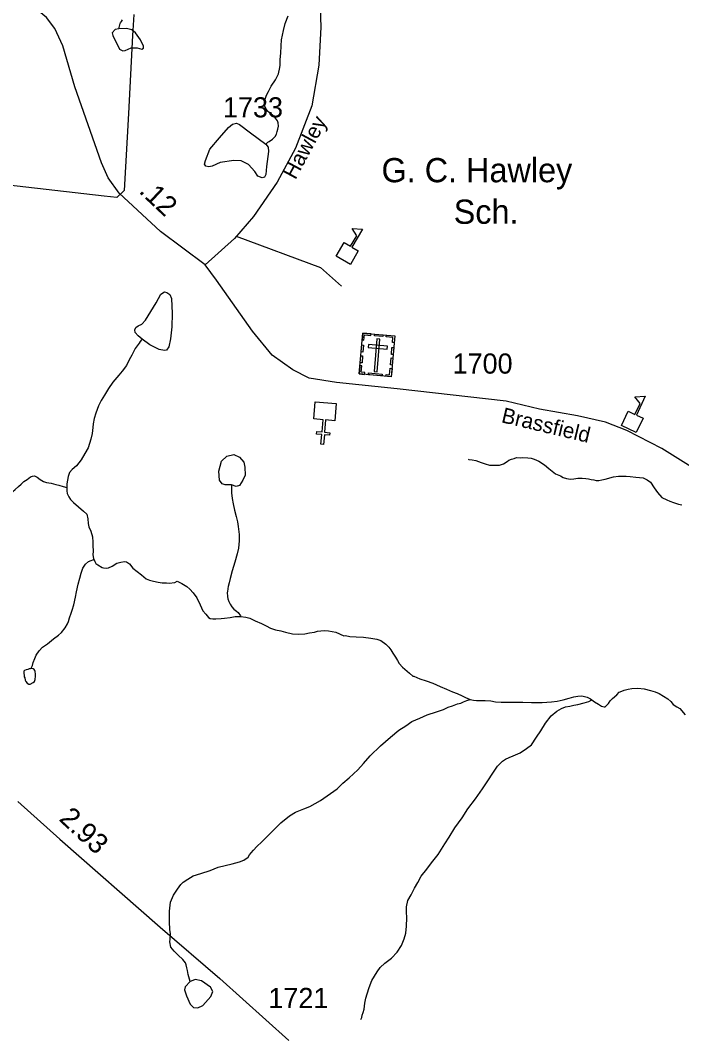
# Model space of a CAD drawing. Extents: x 2056842 to 2160602, y 826753 to 1016856.
# Drawn here: x 2095148 to 2099244, y 853660 to 859964 of the extents above; entities that cross this region are included whole.
import ezdxf

# ---------------------------------------------------------------- set-up
doc = ezdxf.new("R2010")
doc.units = 0
for name, color, linetype in [('Exist Boundary Political City Limit New', 7, 'Continuous'), ('Exist Cultural Cemetery CELL', 7, 'Continuous'), ('Exist Cultural Church CELL', 7, 'Continuous'), ('Exist Cultural Educational Facility High CELL', 7, 'Continuous'), ('Exist Cultural Educational Facility High Label', 7, 'Continuous'), ('Exist Hydrographic Creek Single Shore', 7, 'Continuous'), ('Exist Hydrographic Misc Water Feature', 7, 'Continuous'), ('Exist Road Non-System Type 51', 7, 'Continuous'), ('Exist Road Secondary Mileage Hundredths English Label', 7, 'Continuous'), ('Exist Road Secondary Type 51 Attributed', 7, 'Continuous'), ('Exist Road Secondary Type 51 Label', 7, 'Continuous'), ('Exist Road Secondary Type 51 Number Label', 7, 'Continuous'), ('Map Preparation Boundary City Limit Buffer Line', 7, 'Continuous')]:
    doc.layers.add(name, color=color, linetype=linetype)

msp = doc.modelspace()

# ---------------------------------------------------------------- linework, layer by layer
at = {"layer": 'Exist Boundary Political City Limit New'}
msp.add_lwpolyline([(2095849.9, 860000), (2095844.8, 859902.2), (2095843.1, 859871.1), (2095838.9, 859789.4), (2095817.8, 859386.1), (2095791.2, 858909.4), (2095744.6, 858866.4), (2095668, 858875.1), (2095000, 858950.6)], dxfattribs=at)
at = {"layer": 'Exist Cultural Cemetery CELL'}
for points in [[(2097268.9, 858026.4), (2097467.3, 858009.4), (2097445.6, 857755.7), (2097247.2, 857772.7)], [(2097265.2, 857983.3), (2097276.5, 857982.3), (2097279.3, 858014.4), (2097319.7, 858010.9), (2097320.6, 858022), (2097268.9, 858026.4)], [(2097375.1, 857987.9), (2097356.4, 857989.5), (2097339.2, 857787.5), (2097357.8, 857785.9)], [(2097342.7, 858020.1), (2097394.4, 858015.7), (2097393.4, 858004.3), (2097341.8, 858008.7)], [(2097463.7, 857966.2), (2097452.4, 857967.2), (2097455.1, 857999.3), (2097414.7, 858002.7), (2097415.6, 858013.8), (2097467.3, 858009.4)], [(2097258.9, 857909.4), (2097262.6, 857952.5), (2097273.9, 857951.6), (2097270.2, 857908.4)], [(2097303.8, 857955.1), (2097302.2, 857936.5), (2097419.5, 857926.5), (2097421.1, 857945.1)], [(2097446.1, 857894.4), (2097449.8, 857937.6), (2097461.1, 857936.6), (2097457.4, 857893.4)], [(2097253.1, 857842.4), (2097256.8, 857885.6), (2097268.2, 857884.6), (2097264.5, 857841.4)], [(2097440.4, 857828.7), (2097444.1, 857871.9), (2097455.5, 857870.9), (2097451.8, 857827.7)], [(2097280.2, 857769.9), (2097281.2, 857781.4), (2097259.2, 857783.3), (2097262.7, 857823.5), (2097251.6, 857824.5), (2097247.2, 857772.8)], [(2097412.6, 857758.6), (2097413.6, 857770), (2097435.5, 857768.1), (2097438.9, 857808.4), (2097450, 857807.5), (2097445.6, 857755.7)], [(2097305.4, 857779.3), (2097390, 857772), (2097389, 857760.7), (2097304.5, 857767.9)]]:
    msp.add_lwpolyline(points, close=True, dxfattribs=at)
at = {"layer": 'Exist Cultural Church CELL'}
msp.add_lwpolyline([(2097095.7, 857482.9), (2097039, 857487.6), (2097032.4, 857411.8), (2097064.3, 857409), (2097063, 857393.1), (2097031.1, 857395.9), (2097025.9, 857336), (2097010, 857337.3), (2097015.1, 857397.2), (2096983.2, 857400), (2096984.6, 857415.9), (2097016.5, 857413.2), (2097023, 857489), (2096965.6, 857494.1), (2096974.7, 857600.1), (2097104.8, 857588.9)], close=True, dxfattribs=at)
at = {"layer": 'Exist Cultural Educational Facility High CELL'}
for points in [[(2097104.3, 858502.5), (2097153.6, 858587.1), (2097193.4, 858563.9), (2097231.2, 858628.8), (2097202.8, 858673.4), (2097266.4, 858670.1), (2097201.7, 858559.1), (2097241.4, 858535.9), (2097192.1, 858451.3)], [(2098871.4, 857453.2), (2098913.2, 857541.8), (2098954.8, 857522.2), (2098986.8, 857590.1), (2098954.6, 857632.1), (2099018.2, 857634.3), (2098963.5, 857518.1), (2099005.1, 857498.5), (2098963.4, 857409.9)]]:
    msp.add_lwpolyline(points, close=True, dxfattribs=at)
at = {"layer": 'Exist Hydrographic Creek Single Shore'}
for points in [[(2095034.8, 857051.2), (2095048.9, 857047), (2095068.6, 857043.2), (2095084.8, 857043.2), (2095100.8, 857045.2), (2095116.8, 857057.4), (2095136.9, 857075.4), (2095152.9, 857089.6), (2095168.7, 857105.5), (2095190.6, 857119.6), (2095210.7, 857135.7), (2095222.8, 857139.5), (2095234.7, 857141.8), (2095252.3, 857133.8), (2095270.4, 857119.7), (2095290.3, 857106.1), (2095310.6, 857099.8), (2095338.2, 857096), (2095366.7, 857088.1), (2095386.4, 857084.2), (2095412.9, 857076.2), (2095436.5, 857070.2)], [(2095436.5, 857070.2), (2095436.7, 857048.2), (2095438.7, 857032.5), (2095449, 857012.3), (2095458.6, 856994.6), (2095476.9, 856976.4), (2095507.2, 856948.7), (2095539, 856922.8), (2095558.9, 856904.8), (2095565.4, 856874.6), (2095567.1, 856846.7), (2095571.6, 856824.9), (2095585.5, 856798.9), (2095595.6, 856762.9), (2095597.4, 856730.9), (2095596, 856708.8), (2095598, 856674.8), (2095597.8, 856651), (2095601.7, 856628.8), (2095604, 856624.8)], [(2095604, 856624.8), (2095609.7, 856611), (2095615.9, 856599.1), (2095628.2, 856589.1), (2095654, 856573), (2095663.9, 856571.1), (2095680.3, 856569.1), (2095694.2, 856571), (2095716.2, 856581.4), (2095746.1, 856599.3), (2095769.9, 856607.4), (2095793.9, 856611.5), (2095806, 856607.6), (2095824, 856595.5), (2095843.9, 856569.8), (2095872.2, 856547.7), (2095898.2, 856527.9), (2095926.5, 856504.1), (2095948.5, 856495.9), (2095972.7, 856488.2), (2096002.2, 856482.1), (2096026.4, 856478.5), (2096052.6, 856478.2), (2096070.5, 856476.3), (2096104.3, 856480.5), (2096118.5, 856488.5), (2096148.4, 856474.6), (2096178.1, 856456.7), (2096198.6, 856439), (2096218.3, 856416.9), (2096240.7, 856385.1), (2096261, 856341.1), (2096278.8, 856305.1), (2096296.9, 856283.3), (2096313.1, 856263.4), (2096323.1, 856257.4), (2096339.3, 856255.4), (2096358.8, 856255.2), (2096391.2, 856257.6), (2096413.1, 856259.6), (2096447, 856263.8), (2096479, 856269.9), (2096513, 856269.6)], [(2096513, 856269.6), (2096545, 856266), (2096569.2, 856259.9), (2096603.2, 856242.1), (2096640.9, 856226.3), (2096671.3, 856212.4), (2096696.9, 856198.3), (2096728.9, 856186.6), (2096761.1, 856180.5), (2096790.8, 856172.7), (2096833.3, 856162.6), (2096873.5, 856161), (2096909.6, 856162.8), (2096939.1, 856169.3), (2096969.4, 856173.2), (2096989.1, 856179.2), (2097009, 856181.4), (2097033.2, 856183.5), (2097057, 856181.5), (2097101.3, 856173.5), (2097151.3, 856149.8), (2097161.4, 856151.9), (2097189.3, 856146), (2097227.2, 856143.9), (2097273.1, 856142.2), (2097319.1, 856136.5), (2097355.1, 856128.6), (2097381.4, 856120.5), (2097411.3, 856098.6), (2097431.2, 856080.6), (2097443.1, 856062.9), (2097455.4, 856042.8), (2097471.6, 856016.8), (2097483.5, 855996.7), (2097493.8, 855979), (2097515.7, 855955), (2097544, 855931.2), (2097557.7, 855919.3), (2097579.9, 855901), (2097584.2, 855899.1), (2097621.9, 855883.2), (2097661.9, 855871.5), (2097702.3, 855855.7), (2097748.2, 855835.7), (2097788, 855819.9), (2097824.1, 855803.9), (2097854.4, 855792), (2097884, 855778.2), (2097906.1, 855768.4), (2097934.4, 855756.4)], [(2098688, 855752.5), (2098704.2, 855740.7), (2098728.4, 855726.9), (2098748.5, 855715), (2098764.5, 855708.9), (2098770.2, 855710.8), (2098790.1, 855731), (2098802.2, 855747), (2098815.9, 855761.1), (2098842.2, 855785.2), (2098858, 855801), (2098873.8, 855807.2), (2098887.9, 855813.1), (2098911.9, 855819.2), (2098936.1, 855823.3), (2098972.2, 855825.5), (2099011.8, 855821.6), (2099051.7, 855811.8), (2099079.8, 855803.9), (2099105.9, 855791.9), (2099132.1, 855776.1), (2099158.4, 855760), (2099176.2, 855742.3), (2099192.4, 855724.4), (2099214.1, 855710.1), (2099232.6, 855700.4), (2099266.2, 855660.5)], [(2097934.4, 855756.4), (2097954.1, 855750.5), (2097972.6, 855748.6), (2097994.3, 855748.5), (2098026.5, 855748.5), (2098062.4, 855746.7), (2098090.7, 855740.8), (2098126.5, 855739), (2098164.3, 855739), (2098214.5, 855739.1), (2098260.4, 855739.5), (2098314.4, 855737.3), (2098380.4, 855735.9), (2098438.6, 855740), (2098473.9, 855746), (2098510.2, 855753.9), (2098547.9, 855764.4), (2098576, 855772.4), (2098600.2, 855776.4), (2098626.1, 855778.6), (2098650, 855772.5), (2098658.2, 855770.5), (2098680, 855758.6), (2098688, 855752.5)]]:
    msp.add_lwpolyline(points, dxfattribs=at)
at = {"layer": 'Exist Hydrographic Misc Water Feature'}
for points in [[(2095757.7, 859911.4), (2095765.6, 859945), (2095768, 859949.1), (2095773.6, 859957.2), (2095781.6, 859966.9)], [(2096668, 859196), (2096674, 859204), (2096681.7, 859210.1), (2096688.1, 859214), (2096709.8, 859228.2), (2096718, 859235.8), (2096725.6, 859244), (2096733.6, 859258.2), (2096739.6, 859276), (2096743.7, 859290), (2096747.4, 859308.1), (2096745.7, 859328.2), (2096741.6, 859341.9), (2096735.3, 859350.1), (2096721.3, 859366), (2096709.4, 859375.9), (2096679.3, 859402), (2096664.9, 859425.7), (2096661.2, 859438), (2096659.4, 859447.6), (2096664.9, 859476), (2096672.7, 859500), (2096684.8, 859523.7), (2096702.5, 859555.9), (2096728.7, 859596.2), (2096746.5, 859632), (2096756.2, 859671.9), (2096756.4, 859686.1), (2096758.2, 859722), (2096762.3, 859761.9), (2096764.2, 859806.2), (2096765.8, 859844.2), (2096777.5, 859902), (2096787.6, 859944.4), (2096807.4, 859992)], [(2095757.7, 859911.4), (2095735, 859907.6), (2095717.2, 859887.3), (2095721, 859870.8), (2095762.8, 859784.7), (2095781.8, 859774.6), (2095797, 859777.1), (2095835, 859794.8), (2095871.7, 859793.6), (2095900.8, 859784.7), (2095909.7, 859792.3), (2095911, 859803.7), (2095892, 859843), (2095861.6, 859886), (2095837.5, 859905), (2095804.6, 859913.9), (2095757.7, 859911.4)], [(2096668, 859196), (2096682, 859177.8), (2096684.6, 859151.2), (2096671.9, 859058.7), (2096669.4, 859008.1), (2096660.5, 858992.9), (2096646.6, 858989.1), (2096618.7, 858997.9), (2096601, 859027.1), (2096560.5, 859071.4), (2096516.2, 859094.2), (2096470.6, 859096.7), (2096385.8, 859084.1), (2096335.1, 859061.3), (2096316.1, 859056.2), (2096297.1, 859061.3), (2096289.5, 859072.7), (2096294.6, 859096.7), (2096322.5, 859165.2), (2096380.7, 859236.1), (2096436.4, 859299.5), (2096463, 859321), (2096487.1, 859326.1), (2096506, 859318.5), (2096574.4, 859266.5), (2096668, 859196)], [(2095901.6, 857989.1), (2095878.1, 858009.7), (2095859.1, 858030), (2095856.5, 858046.5), (2095862.9, 858060.4), (2095876.8, 858070.6), (2095899.6, 858082), (2095922.4, 858106), (2095989.5, 858213.7), (2096018.6, 858266.9), (2096041.4, 858280.9), (2096055.3, 858278.3), (2096074.3, 858265.7), (2096083.2, 858240.3), (2096088.2, 858147.8), (2096085.7, 858064.2), (2096078.1, 857990.7), (2096068, 857940.1), (2096054.1, 857921.1), (2096040.1, 857917.3), (2096008.5, 857923.6), (2095950.2, 857954), (2095901.6, 857989.1)], [(2095901.6, 857989.1), (2095898, 857983.8), (2095889.8, 857973.6), (2095883.5, 857963.7), (2095872, 857947.6), (2095859.9, 857931.6), (2095838, 857889.4), (2095822, 857859.4), (2095804.5, 857825.5), (2095778.5, 857789.3), (2095758.2, 857765.2), (2095720.9, 857721.3), (2095694.8, 857683.1), (2095669.2, 857641.1), (2095648.9, 857608.9), (2095631.1, 857575.1), (2095615.1, 857530.8), (2095605.2, 857497), (2095599.5, 857464.7), (2095597.6, 857440.6), (2095593.7, 857404.6), (2095583.5, 857368.8), (2095568.1, 857314.8), (2095548, 857280.5), (2095524.4, 857240.7), (2095496.1, 857204.4), (2095468.5, 857180.6), (2095452.7, 857162.3), (2095444.5, 857138.4), (2095440.4, 857114.2), (2095436.3, 857092.5), (2095436.5, 857070.2)], [(2096455, 857084.9), (2096416.2, 857085.2), (2096398.4, 857091.5), (2096382, 857115.6), (2096378.2, 857171.3), (2096394.6, 857233.4), (2096427.6, 857263.8), (2096469.4, 857273.9), (2096504.8, 857256.2), (2096532.7, 857225.8), (2096537.7, 857195.4), (2096540.3, 857144.7), (2096525.1, 857114.3), (2096506.1, 857082.6), (2096484.5, 857076.3), (2096455, 857084.9)], [(2097921.7, 857244.2), (2097925.6, 857242), (2097945.7, 857240.1), (2097969.5, 857236.1), (2098002.1, 857224.3), (2098027.9, 857216.3), (2098053.8, 857208.3), (2098084.1, 857206.6), (2098115.9, 857208.6), (2098139.7, 857216.8), (2098163.9, 857231.1), (2098173.5, 857238.9), (2098189.9, 857244.9), (2098205.9, 857249), (2098221.7, 857255.1), (2098245.7, 857253.1), (2098259.6, 857255), (2098291.6, 857253), (2098311.7, 857251.2), (2098329.8, 857245.3), (2098359.7, 857233.4), (2098395.6, 857209.7), (2098421.6, 857187.5), (2098462, 857153.8), (2098494, 857141.6), (2098509.8, 857132), (2098531.7, 857124.1), (2098555.7, 857120.1), (2098575.6, 857122), (2098601.9, 857126.1), (2098627.7, 857126.2), (2098650, 857124.5), (2098667.9, 857122.6), (2098683.9, 857118.5), (2098699.7, 857116.5), (2098713.8, 857112.4), (2098731.7, 857112.5), (2098749.9, 857116.6), (2098769.6, 857120.9), (2098821.7, 857135), (2098853.9, 857139), (2098899.8, 857139), (2098925.8, 857137.1), (2098959.9, 857133.1), (2099005.6, 857129.4), (2099029.6, 857117.7), (2099051.9, 857101.7), (2099073.9, 857067.5), (2099094, 857037.7), (2099122.3, 857007.9), (2099152.4, 856992), (2099170.5, 856983.9), (2099194.3, 856976.3), (2099224.4, 856966), (2099244.3, 856962.2)], [(2096455, 857084.9), (2096456.8, 857067.7), (2096456.6, 857051.5), (2096456.6, 857035.7), (2096460.5, 857001.4), (2096466.9, 856967.6), (2096474.9, 856929.4), (2096484.9, 856889.8), (2096493.3, 856855.7), (2096497, 856827.5), (2096503.1, 856777.9), (2096503.8, 856739.6), (2096499.9, 856693.6), (2096491.7, 856657.5), (2096475.7, 856607.5), (2096459.9, 856553.6), (2096448.2, 856505.4), (2096440.4, 856479.4), (2096434.3, 856455.6), (2096432.2, 856443.7), (2096430.8, 856421.7), (2096428.3, 856417.6), (2096430.8, 856393.7), (2096432.6, 856379.6), (2096438.6, 856363.7), (2096446.6, 856345.8), (2096458.9, 856329.7), (2096471, 856315.7), (2096478.7, 856309.7), (2096486.7, 856303.6), (2096497, 856293.9), (2096511.1, 856273.6), (2096513, 856269.6)], [(2095214.2, 855947.9), (2095216, 855953.7), (2095222.4, 855965.7), (2095227.9, 855983.9), (2095238.2, 856010), (2095245.8, 856029.9), (2095263.8, 856056), (2095285.5, 856079.9), (2095315.7, 856100.1), (2095353.4, 856130.4), (2095383.4, 856154.3), (2095403.5, 856170.4), (2095425, 856200.4), (2095439.3, 856224.6), (2095447.1, 856238.4), (2095452.9, 856260.6), (2095462.9, 856290.8), (2095468.9, 856308.5), (2095478.9, 856342.7), (2095488.8, 856388.7), (2095496.5, 856422.8), (2095506.6, 856470.8), (2095516.4, 856506.7), (2095524.2, 856538.7), (2095533.9, 856568.5), (2095552.3, 856594.9), (2095570, 856610.9), (2095585.7, 856617.1), (2095597.8, 856620.9), (2095604, 856624.8)], [(2095214.2, 855947.9), (2095208.4, 855945.9), (2095202.1, 855945.7), (2095194.1, 855941.6), (2095184.5, 855939.8), (2095174.4, 855935.6), (2095169.9, 855931.8), (2095170.1, 855917.6), (2095172.4, 855903.5), (2095172.4, 855895.8), (2095176.1, 855889.5), (2095178.5, 855875.8), (2095182.4, 855865.9), (2095190.4, 855855.7), (2095200.5, 855849.7), (2095208.4, 855849.7), (2095226.5, 855860), (2095236.1, 855867.9), (2095240.2, 855879.8), (2095242.3, 855899.8), (2095242.3, 855914), (2095240.4, 855926), (2095240, 855931.8), (2095238.2, 855935.7), (2095234.1, 855942), (2095227.9, 855945.8), (2095214.2, 855947.9)], [(2096199.7, 854007.1), (2096188, 854051.1), (2096183.7, 854075.3), (2096179.8, 854092.9), (2096175.5, 854111), (2096169.9, 854123.2), (2096153.7, 854143.1), (2096151.3, 854147.1), (2096127.5, 854169), (2096101.5, 854194.8), (2096079.5, 854220.5), (2096073.4, 854252.7), (2096075, 854270.7), (2096077, 854302.9), (2096074.8, 854330.7), (2096071.1, 854376.8), (2096070.9, 854444.5), (2096078.7, 854498.6), (2096096.1, 854543), (2096120.3, 854580.7), (2096142.1, 854609.1), (2096156.2, 854622.7), (2096185.9, 854640.9), (2096217.7, 854663.3), (2096265.9, 854677.1), (2096323.9, 854695.5), (2096374, 854715.5), (2096415.6, 854725.9), (2096459.7, 854737.8), (2096505.4, 854750), (2096531.9, 854760.2), (2096559.5, 854778.3), (2096567.7, 854792.1), (2096577.4, 854804.4), (2096591.5, 854822.2), (2096613.5, 854844.4), (2096643.2, 854872.3), (2096647.3, 854876.6), (2096693, 854922.4), (2096724.8, 854954.5), (2096761.1, 854990.8), (2096814.6, 855035), (2096852.4, 855056.9), (2096904.6, 855077.4), (2096940.5, 855091.4), (2097006.3, 855129.3), (2097048, 855157.5), (2097110.3, 855202), (2097146, 855235.9), (2097183.9, 855270), (2097237.4, 855320.3), (2097273.5, 855358.3), (2097315.6, 855406.2), (2097379.5, 855468.8), (2097441.1, 855522.8), (2097492.7, 855564.8), (2097534.8, 855592.9), (2097572.7, 855619.2), (2097622.9, 855639.2), (2097668.7, 855659.5), (2097726.5, 855679.5), (2097768.7, 855693.8), (2097798.3, 855708), (2097824.3, 855715.9), (2097856.1, 855728.1), (2097876.4, 855732.3), (2097892.6, 855740), (2097914.1, 855750.1), (2097934.4, 855756.4)], [(2097256.7, 853772.3), (2097262.5, 853784.4), (2097266.1, 853798.4), (2097272.1, 853816.6), (2097278.4, 853836.4), (2097282.1, 853874.3), (2097288.1, 853904.6), (2097296.3, 853930.6), (2097308, 853970.6), (2097326, 854014.6), (2097357.4, 854068.6), (2097377.5, 854094.8), (2097405.4, 854121), (2097447.6, 854153.2), (2097481.2, 854189.1), (2097509.1, 854231.1), (2097525.1, 854271.3), (2097535, 854307.1), (2097540.5, 854351.3), (2097542.6, 854401.3), (2097540.3, 854439.4), (2097540.1, 854471.5), (2097548.1, 854509.2), (2097568.2, 854545.5), (2097589.7, 854585.3), (2097609.8, 854621.6), (2097631.3, 854659.7), (2097665.6, 854703.6), (2097695.1, 854743.8), (2097735.3, 854795.7), (2097776.9, 854860), (2097804.8, 854902), (2097838.7, 854960.2), (2097884.8, 855022.2), (2097920.5, 855078.5), (2097968.2, 855140.6), (2098010.1, 855200.8), (2098043.9, 855250.9), (2098073.6, 855298.7), (2098103.4, 855342.9), (2098135.2, 855372.9), (2098153.4, 855385.2), (2098175.6, 855395.2), (2098201.2, 855407.2), (2098243.4, 855425.1), (2098283.4, 855451.5), (2098313.3, 855475.4), (2098344.9, 855521.7), (2098371, 855561.6), (2098400.9, 855607.8), (2098436.6, 855653.9), (2098470.4, 855684.1), (2098500.4, 855700.2), (2098524.6, 855710), (2098552.4, 855714.2), (2098576.4, 855720.4), (2098600.4, 855724.4), (2098640.4, 855734.6), (2098670.1, 855742.7), (2098688, 855752.5)], [(2096199.7, 854007.1), (2096169.3, 853975.4), (2096164.2, 853955.1), (2096176.9, 853919.6), (2096199.7, 853866.4), (2096221.2, 853846.2), (2096247.8, 853844.9), (2096278.2, 853858.8), (2096328.8, 853914.6), (2096340.2, 853945), (2096326.3, 853972.9), (2096270.6, 854012.1), (2096230, 854019.7), (2096216.1, 854014.7), (2096199.7, 854007.1)]]:
    msp.add_lwpolyline(points, dxfattribs=at)
at = {"layer": 'Exist Road Non-System Type 51'}
msp.add_lwpolyline([(2096485.6, 858626.1), (2097007.6, 858432.9), (2097136.4, 858316.5)], dxfattribs=at)
at = {"layer": 'Exist Road Secondary Type 51 Attributed'}
for points in [[(2096819.9, 863367.2), (2096834.5, 863240.4), (2096830.3, 862999.4), (2096827.2, 862241.8), (2096848, 861855.2), (2096876, 861363.7), (2096962.2, 860541.7), (2097001.6, 860167.6), (2097010, 859922.4), (2096996.5, 859686.5), (2096952.8, 859435), (2096853.1, 859173.1), (2096737.9, 858962.2), (2096592.5, 858748.1), (2096474.1, 858613), (2096292.4, 858449.9)], [(2096292.4, 858449.9), (2096015.1, 858656.7), (2095761, 858892.7), (2095692.5, 858988.3), (2095649.6, 859080.7), (2095484.5, 859551.4), (2095411.8, 859807), (2095360.9, 859914.1), (2095309, 859982.7), (2095232.1, 860045), (2095049.4, 860146.8), (2094696.3, 860342.2), (2094155.3, 860601), (2093820.9, 860794.2), (2093645.4, 860909.6), (2093560.2, 860999), (2093425.2, 861100.8), (2093248.7, 861213), (2093084.6, 861298.2), (2092907, 861367.9), (2092581, 861453.1), (2092455.8, 861485.8)], [(2100713.3, 856564.4), (2100580.1, 856555.5), (2100336.1, 856533.6), (2100209.4, 856548.2), (2100084.8, 856618.9), (2099941.5, 856737.3), (2099747.3, 856910.9), (2099628.9, 856991.9), (2099385.9, 857145.7), (2099122.2, 857309.9), (2098905.1, 857423.2), (2098772.2, 857473.1), (2098599.8, 857512.5), (2098363.1, 857554.1), (2098157.4, 857604), (2097481.4, 857679.9), (2097105.5, 857719.3), (2096937.3, 857746.4), (2096835.5, 857798.3), (2096706.7, 857889.8), (2096586.3, 858037.3), (2096363, 858354.3), (2096292.4, 858449.9)], [(2095131.4, 855123.5), (2095393.1, 854890.7), (2096013, 854345.2), (2096382.7, 854027.2), (2096811.6, 853641.6)]]:
    msp.add_lwpolyline(points, dxfattribs=at)
at = {"layer": 'Map Preparation Boundary City Limit Buffer Line'}
msp.add_lwpolyline([(2095849.9, 860000), (2095844.8, 859902.2), (2095843.1, 859871.1), (2095838.9, 859789.4), (2095817.8, 859386.1), (2095791.2, 858909.4), (2095744.6, 858866.4), (2095668, 858875.1), (2095000, 858950.6)], dxfattribs=at)

# ---------------------------------------------------------------- texts
at = {"layer": 'Exist Cultural Educational Facility High Label'}
for s, p in [('G. C. Hawley', (2097385.1, 858960.9)), ('Sch.', (2097832.3, 858703.3))]:
    msp.add_text(s, height=150, dxfattribs=at).set_placement(p)
at = {"layer": 'Exist Road Secondary Mileage Hundredths English Label'}
for s, rotation, p in [('.12', 316.71756, (2095877.4, 858900.2)), ('2.93', 317.17753, (2095382.1, 855009.1))]:
    msp.add_text(s, height=125, rotation=rotation, dxfattribs=at).set_placement(p)
at = {"layer": 'Exist Road Secondary Type 51 Label'}
for s, rotation, p in [('Hawley', 61.71686, (2096851.5, 858972.2)), ('Brassfield', 346.68511, (2098122.5, 857474))]:
    msp.add_text(s, height=95, rotation=rotation, dxfattribs=at).set_placement(p)
at = {"layer": 'Exist Road Secondary Type 51 Number Label'}
for s, p in [('1733', (2096402.8, 859362.8)), ('1700', (2097825.2, 857774.9)), ('1721', (2096684.2, 853843))]:
    msp.add_text(s, height=125, dxfattribs=at).set_placement(p)

doc.saveas('drawing.dxf')
